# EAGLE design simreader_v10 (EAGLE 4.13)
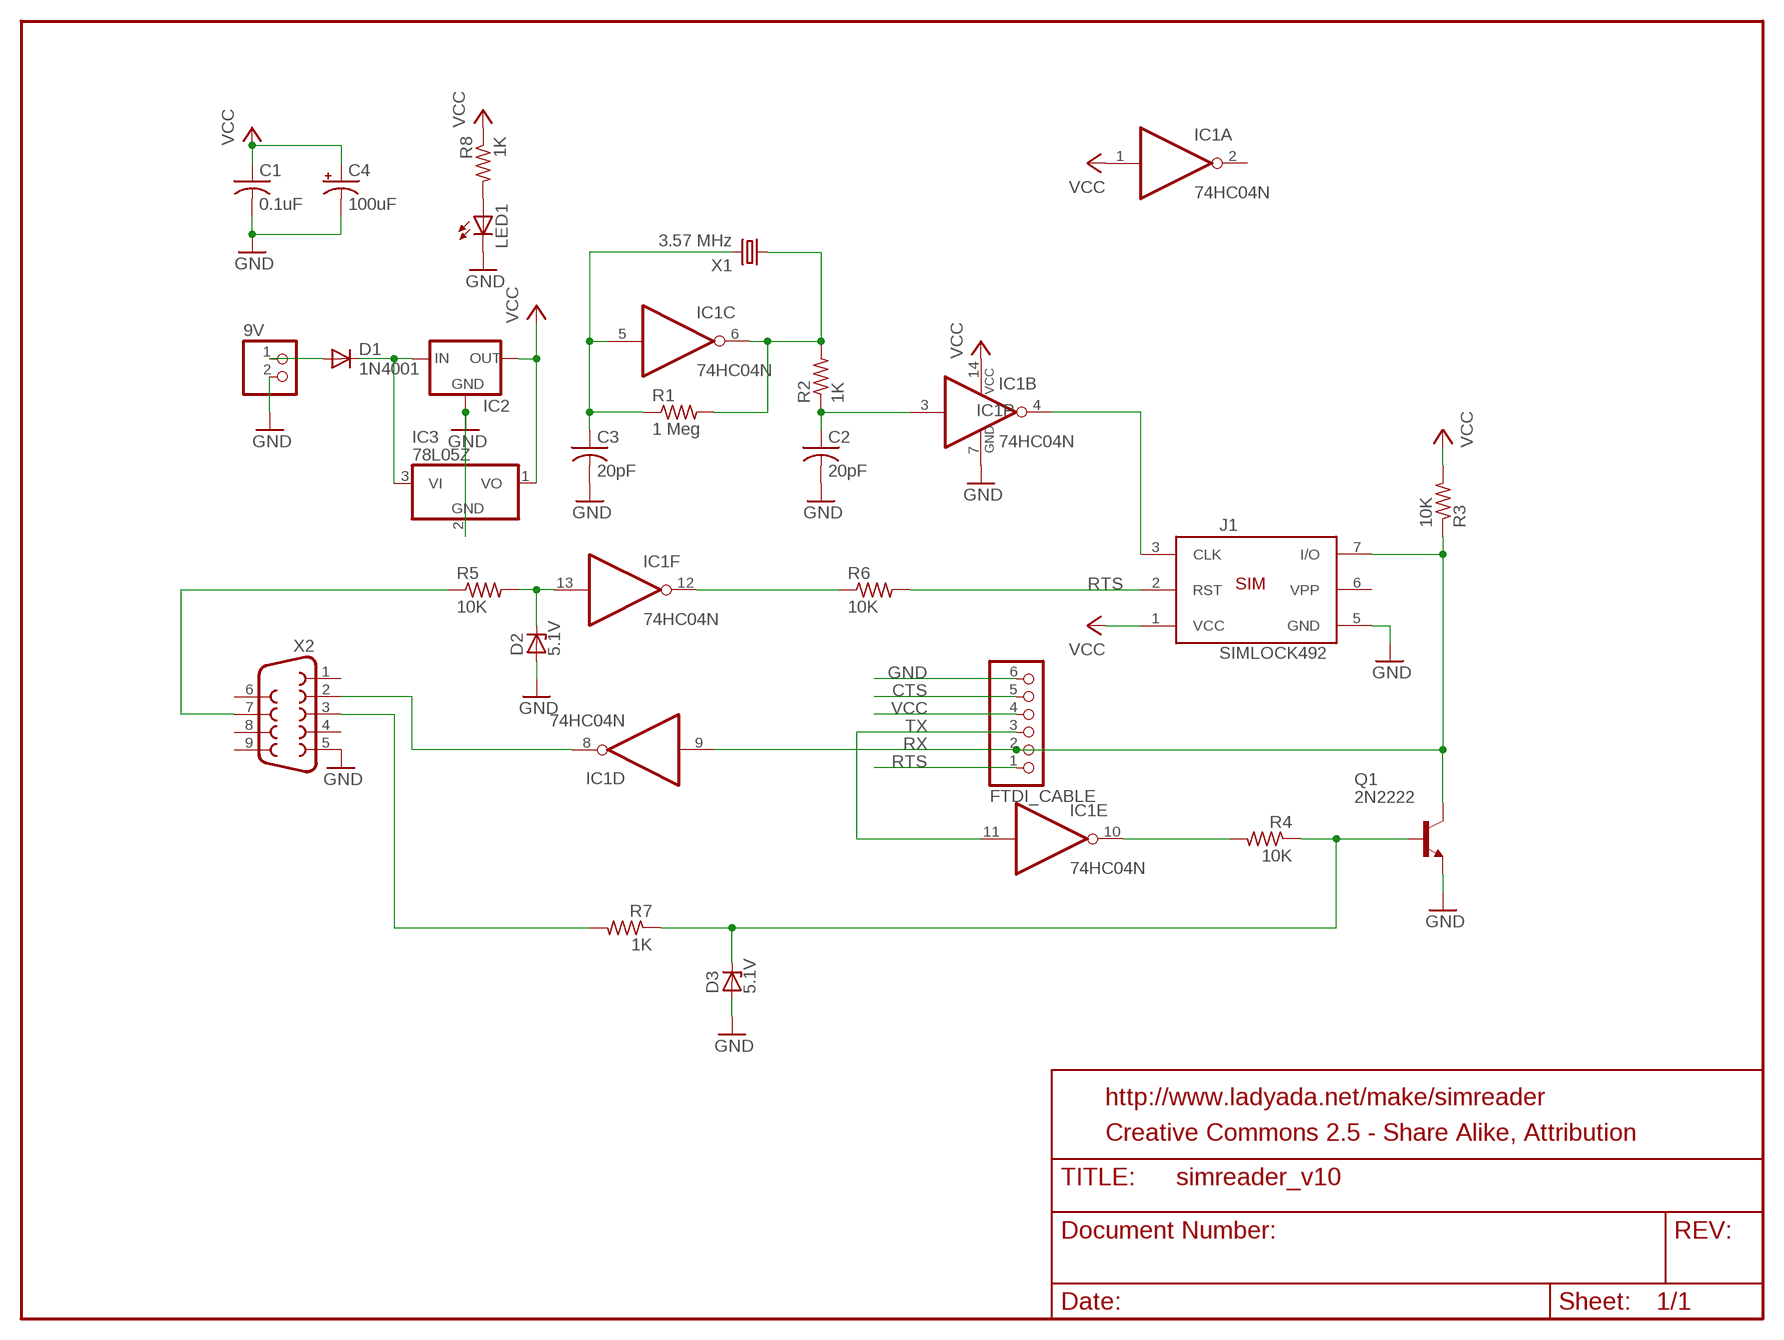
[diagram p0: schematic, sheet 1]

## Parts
9V  PINHD-1X2  [1X02]
C1  0.1uF  C-US025-025X050  [C025-025X050]
C2  20pF  C-US025-025X050  [C025-025X050]
C3  20pF  C-US025-025X050  [C025-025X050]
C4  100uF  CPOL-USE2.5-5  [E2,5-5]
D1  1N4001  1N4004  [DO41-10]
D2  5.1V  ZENER-DIODEDO35Z10  [DO35Z10]
D3  5.1V  ZENER-DIODEDO35Z10  [DO35Z10]
FTDI_CABLE  PINHD-1X6  [1X06]
IC1  74HC04N  [DIL14]
IC2  78XXS  [78XXS]
IC3  78L05Z  [TO92]
J1  SIMLOCK492  [5002]
LED1  LED3MM  [LED3MM]
Q1  2N2222  [TO92-EBC]
R1  1 Meg  R-US_0207/10  [0207/10]
R2  1K  R-US_0207/10  [0207/10]
R3  10K  R-US_0207/10  [0207/10]
R4  10K  R-US_0207/10  [0207/10]
R5  10K  R-US_0207/10  [0207/10]
R6  10K  R-US_0207/10  [0207/10]
R7  1K  R-US_0207/10  [0207/10]
R8  1K  R-US_0207/10  [0207/10]
X1  3.57 MHz  CRYSTAL  [HC49]
X2  F09D  [F09D]

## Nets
CTS: FTDI_CABLE.5
GND: 9V.2 C1.2 C2.2 C3.2 C4.- D2.A D3.A FTDI_CABLE.6 IC1.7(P:GND) IC2.GND IC3.2(GND) J1.5(GND) LED1.K(C) Q1.E X2.5
N$1: C3.1 IC1.5(C:I) R1.1 X1.2
N$2: IC1.6(C:O) R1.2 R2.2 X1.1
N$3: C2.1 IC1.3(B:I) R2.1
N$4: IC1.10(E:O) R4.2
N$5: IC1.4(B:O) J1.3(CLK)
N$6: D3.C Q1.B R4.1 R7.1
N$7: D1.C IC2.IN IC3.3(VI)
N$8: IC1.8(D:O) X2.2
N$9: R5.1 X2.7
N$10: D2.C IC1.13(F:I) R5.2
N$11: IC1.12(F:O) R6.1
N$12: R7.2 X2.3
N$13: LED1.A R8.2
N$14: 9V.1 D1.A
RTS: FTDI_CABLE.1 J1.2(RST) R6.2
RX: FTDI_CABLE.2 IC1.9(D:I) J1.7(I/O) Q1.C R3.1
TX: FTDI_CABLE.3 IC1.11(E:I)
VCC: C1.1 C4.+ FTDI_CABLE.4 IC1.1(A:I) IC1.14(P:VCC) IC2.OUT IC3.1(VO) J1.1(VCC) R3.2 R8.1
Unconnected: IC1.2(A:O) J1.6(VPP) X2.1 X2.4 X2.6 X2.8 X2.9

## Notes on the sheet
- http://www.ladyada.net/make/simreader
- Creative Commons 2.5 - Share Alike, Attribution

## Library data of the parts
9V = pinhead:PINHD-1X2: PIN HEADER
C1-C3 = rcl-ez:C-US: CAPACITOR, American symbol
C4 = rcl-ez:CPOL-US: POLARIZED CAPACITOR, American symbol
D1 = diode:1N4004: DIODE
D2 D3 = diode:ZENER-DIODE: Z-Diode
FTDI_CABLE = pinhead:PINHD-1X6: PIN HEADER
IC1 = 74xx-eu:74*04: Hex INVERTER
IC2 = v-reg:78XXS: VOLTAGE REGULATOR
IC3 = linear-ez:78*: Positive VOLTAGE REGULATOR
J1 = sim:SIMLOCK492
LED1 = led-ez:LED: LED
Q1 = sim:2N2222: NPN TRANSISTOR
R1-R8 = rcl-ez:R-US_: RESISTOR, American symbol
X1 = sim:CRYSTAL
X2 = con-subd:F09: SUB-D

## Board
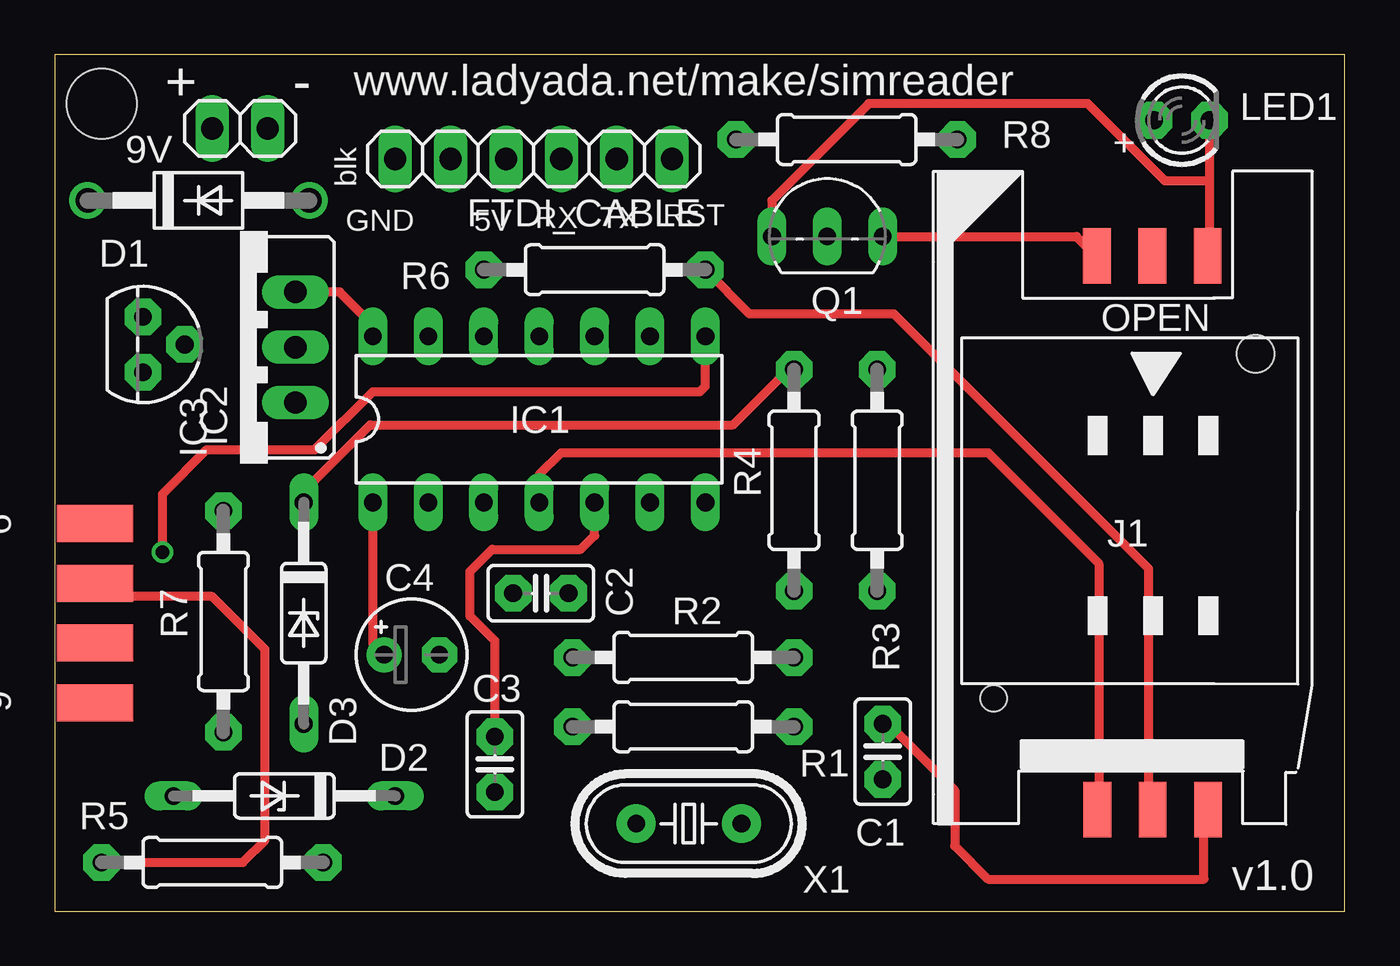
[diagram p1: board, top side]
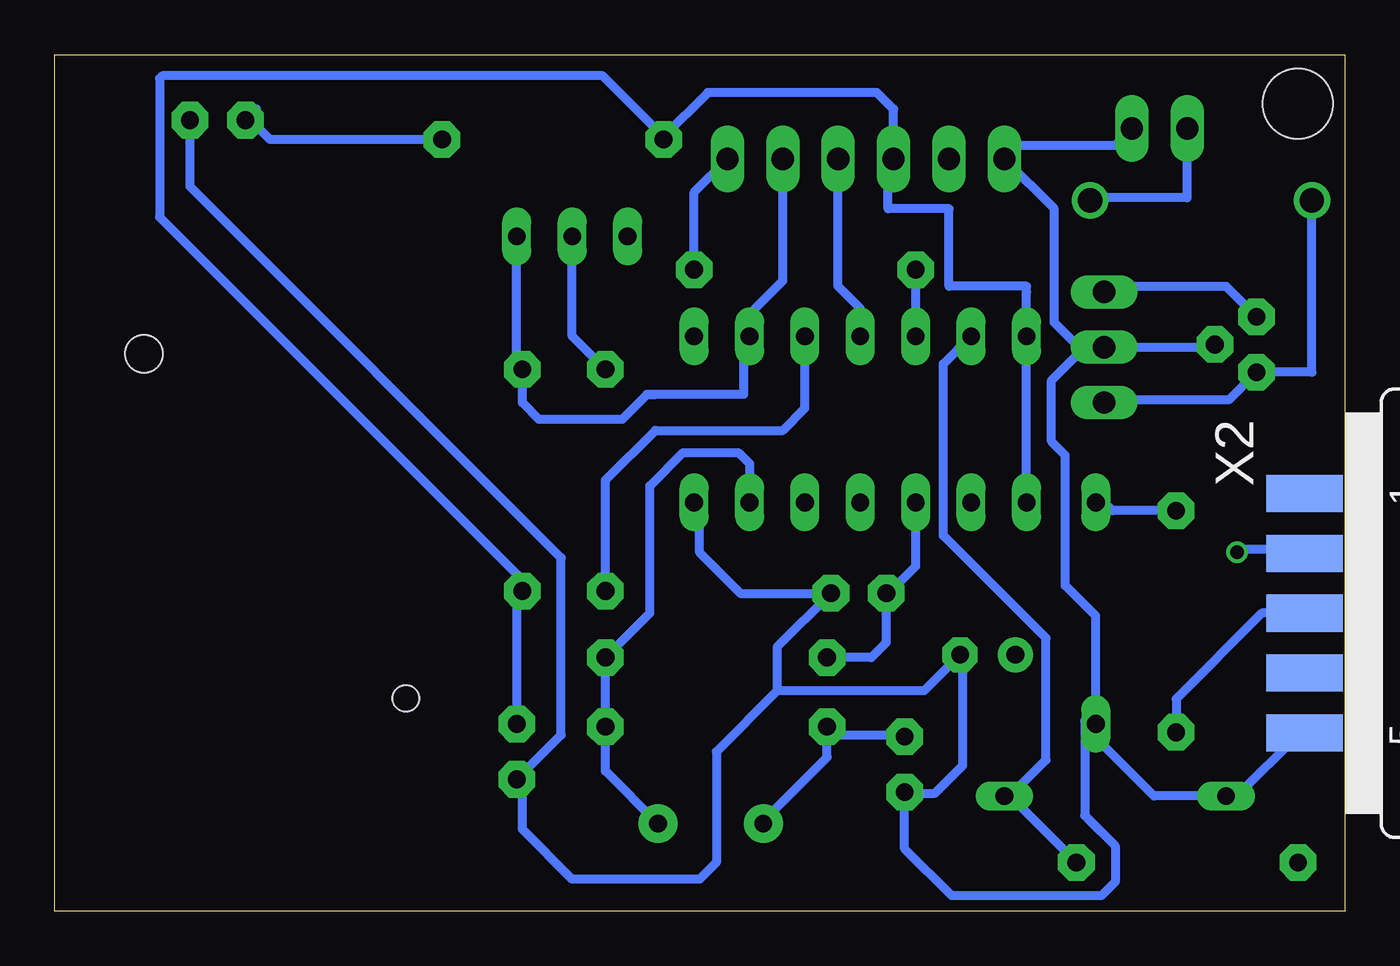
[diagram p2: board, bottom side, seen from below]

Size 59.16 x 39.29 mm. Coordinates in mm from the lower left corner, seen from the top.
Outline: 0,0 59.16,0 59.16,39.29 0,39.29 0,0
Copper layers (1*16): Top 0.035mm / dielectric 1.5mm / Bottom 0.035mm
Design rules "default": minimum track width 10mil, minimum drill 20mil, track to track 12mil, track to pad 12mil, pad to pad 12mil, via to via 12mil, smd to smd 0mil, copper to edge 10mil, drill to drill 8mil, minimum pad ring 10mil, minimum via ring 8mil, stop-mask expansion 4mil, vias tented up to drill 0mil, thermal gap 10mil
Holes 3.2 mm at 2.15,37.05

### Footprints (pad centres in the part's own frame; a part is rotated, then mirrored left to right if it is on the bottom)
1X02 = drill 1.016 long: 1 -1.27,0; 2 1.27,0
C025-025X050 = drill 0.813 pad 1.676 octagon: 1 -1.27,0; 2 1.27,0
E2,5-5 = drill 0.813 pad 1.6 round: + -1.27,0 | drill 0.813 pad 1.6 octagon: - 1.27,0
DO41-10 = drill 1.118 round: A 5.08,0; C -5.08,0
DO35Z10 = drill 0.813 long: A 5.08,0; C -5.08,0
1X06 = drill 1.016 long: 1 -6.35,0; 2 -3.81,0; 3 -1.27,0; 4 1.27,0; 5 3.81,0; 6 6.35,0
DIL14 = drill 0.813 long: 1 -7.62,-3.81; 2 -5.08,-3.81; 3 -2.54,-3.81; 4 0,-3.81; 5 2.54,-3.81; 6 5.08,-3.81; 7 7.62,-3.81; 8 7.62,3.81; 9 5.08,3.81; 10 2.54,3.81; 11 0,3.81; 12 -2.54,3.81; 13 -5.08,3.81; 14 -7.62,3.81
78XXS = drill 1.016 long: GND 0,-2.54; IN -2.54,-2.54; OUT 2.54,-2.54
TO92 = drill 0.813 pad 1.676 octagon: 1 -1.27,0; 2 0,1.905; 3 1.27,0
5002 = smd 2.54 x 1.27: 1 0.904,0.574; 2 0.904,3.114; 3 0.904,5.654; 5 26.299,0.594; 6 26.299,3.134; 7 26.299,5.674 | hole 1.7: 21.8,-1.6 | hole 1.2: 6,10.4
LED3MM = drill 0.813 pad 1.676 octagon: A -1.27,0; K 1.27,0
TO92-EBC = drill 0.813 long: B 0,-1.27; C 2.54,-1.27; E -2.54,-1.27
0207/10 = drill 0.813 pad 1.676 octagon: 1 -5.08,0; 2 5.08,0
HC49 = drill 0.813 pad 1.778 round: 1 -2.413,0; 2 2.413,0
F09D = smd 1.7 x 3.5: 1 -5.486,-6.045; 2 -2.743,-6.045; 3 0,-6.045; 4 2.743,-6.045; 5 5.486,-6.045 | smd 1.7 x 3.5 bottom: 6 -4.115,-6.045; 7 -1.372,-6.045; 8 1.372,-6.045; 9 4.115,-6.045

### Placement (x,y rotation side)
9V  8.5,35.9 0 top
C1  37.97,7.33 270 top
C2  22.3,14.59 0 top
C3  20.19,6.74 270 top
C4  16.38,11.77 0 top
D1  6.6,32.6 0 top
D2  10.54,5.3 180 top
D3  11.43,13.68 270 top
FTDI_CABLE  21.97,34.51 180 top
IC1  22.22,22.57 0 top
IC2  8.5,25.87 90 top
IC3  4.06,26 270 top
J1  53.46,3.77 90 top
LED1  51.68,36.28 0 top
Q1  35.43,32.22 0 top
R1  28.82,8.47 0 top
R2  28.82,11.65 0 top
R3  37.71,19.77 270 top
R4  33.9,19.77 270 top
R5  7.23,2.25 0 top
R6  24.76,29.43 0 top
R7  7.74,13.3 270 top
R8  36.32,35.4 0 top
X1  29.08,4.03 180 top
X2  -4.2,13.68 270 bottom

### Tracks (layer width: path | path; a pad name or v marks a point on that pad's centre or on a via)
GND
  Top 0.406: J1.5 52.95,30.16 52.95,33.49 | LED1.K 52.95,34.51 | 52.95,34.51 52.95,34.25 | 52.95,34.51 52.95,33.49 | Q1.E 32.89,32.6 37.33,37.05 47.37,37.05 50.92,33.49 52.95,33.49
  Bottom 0.406: IC1.7 29.59,18.5 29.59,16.47 27.68,14.57 23.54,14.57 | 26.03,10.12 28.82,7.33 28.82,2.25 29.59,1.49 35.43,1.49 37.71,3.77 37.71,6.31 C1.2 35.94,8.09 35.94,16.22 52.95,33.24 LED1.K 52.95,36.54 | 26.03,10.12 19.3,10.12 C4.- 17.52,11.77 17.52,6.69 18.79,5.42 20.19,5.42 | 10.54,3.01 11.81,4.28 | 10.54,3.01 10.54,1.36 11.17,0.72 18.03,0.72 20.19,2.88 20.19,5.42 | D3.A 11.43,7.96 8.76,5.3 D2.A 5.71,5.04 5,5.04 5,5.25 2.05,8.19 X2.5 | 10.54,3.01 11.93,4.41 11.93,8.72 11.43,8.72 D3.A | 9V.2 10.54,35.14 14.98,35.14 FTDI_CABLE.6 13.33,32.22 13.33,27.01 12.06,25.74 | IC2.GND 11.17,25.87 | IC3.2 6.09,25.87 IC2.GND | 12.06,25.74 11.17,25.74 IC2.GND | 12.06,25.74 13.46,24.35 13.46,21.55 12.82,20.92 12.82,14.95 11.43,13.55 D3.A | 20.19,5.42 C3.2 | 23.54,14.57 23.49,14.57 | 23.54,14.57 C2.2 26.03,12.13 26.03,10.12
N$1
  Top 0.406: IC1.5 24.76,17.23 24.12,16.6 20.06,16.6 19.04,15.58 19.04,13.55 20.19,12.41 C3.1
  Bottom 0.406: X1.2 26.79,4.03 23.74,7.07 R1.1 23.36,8.09 20.19,8.09 C3.1
N$2
  Bottom 0.406: X1.1 33.9,6.44 R1.2 R2.2 31.87,13.68 31.87,19.52 30.35,21.04 27.81,21.04 27.3,20.54 IC1.6
N$3
  Bottom 0.406: R2.1 23.74,11.9 | IC1.3 19.68,15.84 20.95,14.57 20.97,14.59 C2.1 21.03,12.33 21.71,11.65 R2.1 | R2.1 23.87,11.77
N$4
  Bottom 0.406: IC1.10 24.76,23.08 25.78,22.06 31.62,22.06 33.9,19.77 R4.2
N$5
  Top 0.406: IC1.4 22.22,20.03 23.24,21.04 42.79,21.04 47.87,15.96 47.87,4.79 47.81,4.72 J1.3
N$6
  Top 0.406: R4.1 33.65,24.85 31.11,22.31 14.47,22.31 11.3,19.14 11.43,19.01 D3.C
  Bottom 0.406: R4.1 35.43,26.38 Q1.B | D3.C 11.43,18.88 11.3,19.01 10.66,18.38 R7.1
N$7
  Bottom 0.406: IC2.IN 10.92,23.46 5.33,23.46 IC3.3 1.52,24.73 D1.C
N$8  (via drill 0.6)
  Top 0.406: IC1.8 29.84,24.09 29.59,23.84 14.6,23.84 11.93,21.17 6.98,21.17 4.95,19.14 v4.95,16.47
  Bottom 0.406: X2.2 2.03,16.6 4.82,16.6 v4.95,16.47
N$9
  Top 0.406: 1.9,2.25 R5.1 8.63,2.25 9.65,3.26 9.65,12.03 7.23,14.44 2.46,14.44 X2.7
N$10
  Bottom 0.406: R5.2 15.36,5.3 | IC1.13 18.41,25.11 18.41,18.63 18.41,17.23 13.71,12.54 13.71,6.95 15.36,5.3 | 15.36,5.3 D2.C
N$11
  Bottom 0.406: IC1.12 R6.1
N$12
  Bottom 0.406: R7.2 7.74,9.74 3.8,13.68 X2.3
N$13
  Bottom 0.406: 50.29,36.41 49.91,36.79 | 50.29,36.41 LED1.A | R8.2 49.27,35.4 50.29,36.41
N$14
  Bottom 0.406: D1.A 11.68,32.73 7.23,32.73 9V.1
RTS
  Top 0.406: R6.2 31.87,27.39 38.48,27.39 50.16,15.71 50.16,4.79 50.24,4.79 J1.2
  Bottom 0.406: FTDI_CABLE.1 29.84,32.98 R6.2
RX
  Top 0.406: 47.87,29.93 47.87,29.98 J1.7 47.74,30.07 46.86,30.95 Q1.C
  Bottom 0.406: Q1.C 37.97,25.11 R3.1 37.71,23.33 36.95,22.57 33.14,22.57 32,23.71 | FTDI_CABLE.2 25.78,28.92 27.05,27.65 27.05,26.89 27.55,26.38 | 27.55,26.38 IC1.9 | 27.55,26.38 27.55,23.71 32,23.71 | 32,23.71 31.62,23.71
TX
  Bottom 0.406: FTDI_CABLE.3 23.24,28.66 22.22,27.65 IC1.11
VCC
  Top 0.406: J1.1 52.7,4.49 52.7,1.49 42.79,1.49 41.27,3.01 41.27,5.55 38.22,8.6 C1.1 | IC1.1 14.6,12.28 C4.+ | IC2.OUT 13.08,28.41 14.47,27.01 14.47,26.63 14.6,26.5 IC1.14
  Bottom 0.406: 14.6,28.41 14.6,27.14 14.85,26.89 14.85,26.38 IC1.14 | IC1.14 14.6,28.66 18.16,28.66 18.16,32.22 20.95,32.22 20.95,34.51 FTDI_CABLE.4 20.7,36.79 21.46,37.55 29.2,37.55 31.24,35.52 | IC1.1 IC1.14 | C1.1 37.97,14.44 R3.2 37.46,14.95 54.35,31.84 54.35,38.19 54.22,38.32 34.03,38.32 31.24,35.52 | 31.24,35.52 R8.1 | IC2.OUT 11.04,28.66 5.46,28.66 IC3.1

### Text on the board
tPlace: + | - | www.ladyada.net/make/simreader | + | blk | RST | GND | 5V | RX | TX | v1.0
